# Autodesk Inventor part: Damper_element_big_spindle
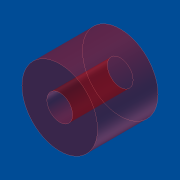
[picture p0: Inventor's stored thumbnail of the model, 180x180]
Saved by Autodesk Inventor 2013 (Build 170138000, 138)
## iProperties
Shininess: 20.0
Length Units: 11269
Angle Units: 11279
Time Units: 11290
Mass Units: 11283
Length Display Precision: 3
Angle Display Precision: 2
Created: 2001-04
Part Number: Damper_element_big_spindle
Material: Standard
Document SubType Name: Modellieren
Designer: dl
Density: 1 g/cm^3
Density: 0.0
Volumn: 0.0
Area: 0.0
PropertySet Name: Model Information
Control State: 0
Master: False
Checked Out: False
Author: dl
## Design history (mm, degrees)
body "Solid1"
sketch "Sketch1"
  geometry: C1 r 12.5 at (0, 0); C2 r 4.25 at (0, 0)
  constraints: 2 centre point, 1 coincident
  dimensions: "d0" = 25 diameter of C1; "d1" = 8.5 diameter of C2
extrude "Extrusion1" new body sketch "Sketch1" distance "d2" = 20; taper "d3" = 0 deg
